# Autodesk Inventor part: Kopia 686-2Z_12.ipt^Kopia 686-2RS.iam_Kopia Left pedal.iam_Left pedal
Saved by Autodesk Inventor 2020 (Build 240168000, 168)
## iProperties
Created: 2017-10
Part Number: Kopia 686-2Z_12.ipt^Kopia 686-2RS.iam_Kopia Left pedal.iam_Left pedal
Material: Ogólny
Document SubType Name: Modeling
Designer: Tomasz
Density: 1 g/cm^3
Appearance: Domyślna
Sending System: SolidWorks 2017
Last Author: Tomasz
Last Saved: 2017-10-01
Author: Tomasz
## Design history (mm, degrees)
